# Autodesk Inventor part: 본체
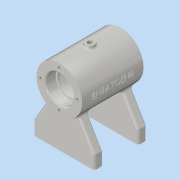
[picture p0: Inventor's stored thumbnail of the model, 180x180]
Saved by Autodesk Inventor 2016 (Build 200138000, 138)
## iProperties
Created: 2018-05
Part Number: 본체
Material: 알루미늄 6061
Document SubType Name: Modeling
Designer: 605-17
Density: 2.7 g/cm^3
Appearance: 알루미늄 - 평지
Mass: 317.791 g
Surface Area: 375.834 cm^2
Volume: 117.701 cm^3
Author: 605-17
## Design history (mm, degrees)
sketch "스케치1"
  geometry: C1 r 26 at (0, 65); 1 further point
  constraints: 1 centre point, 1 vertical alignment
  dimensions: "d0" = 52 diameter of C1; "d1" = 65 distance of point (0, 0) C1.centre
extrude "돌출1" new body sketch "스케치1" stored distance "d2" = 70; taper "d3" = 0 deg
node "작업 평면1"
sketch "스케치3"
  geometry: L1 (-35, 0)-(35, 0); L2 (-35, 0)-(-35, 15); L3 (-35, 15)-(-16.058, 47.808); L4 (-16.058, 47.808)-(16.058, 47.808); L5 (35, 0)-(35, 15); L6 (35, 15)-(16.058, 47.808); 2 further points
  constraints: 12 end point, 2 horizontal, 2 vertical, 1 coincident, 1 midpoint
  dimensions: "d5" = 70 distance of L1.start L1.end; "d6" = 15 distance of L1.start L2.end; "d7" = 30 deg angle of L2 L3; "d8" = 15 distance of L1.end L5.end; "d9" = 30 deg angle of L5 L6; "d10" = 32.11665 distance of L3.end L4.end
extrude "돌출2" join sketch "스케치3" distance "d11" = 10; taper "d12" = 0 deg
sketch "스케치4"
  geometry: L1 (81, 35)-(65, 35); L2 (65, 35)-(65, 23); L3 (65, 23)-(81, 23); L4 (81, 23)-(81, 35); L5 (79, 23)-(65, 23); L6 (65, 23)-(65, 21); L7 (65, 21)-(79, 21); L8 (79, 21)-(79, 23); L9 (86, 21)-(65, 21); L10 (65, 21)-(65, -21); L11 (65, -21)-(86, -21); L12 (86, -21)-(86, 21); L13 (79, -21)-(65, -21); L14 (65, -21)-(65, -23); L15 (65, -23)-(79, -23); L16 (79, -23)-(79, -21); L17 (91, 35)-(39, 35) reference; L18 (81, -23)-(65, -23); L19 (65, -23)-(65, -35); L20 (65, -35)-(81, -35); L21 (81, -35)-(81, -23); 1 further point
  constraints: 40 end point, 10 parallel, 7 collinear, 5 horizontal, 5 perpendicular, 1 midpoint, 1 point on line
  dimensions: "d13" = 12 distance of L1.end L2.end; "d15" = 42 distance of L9.end L10.end; "d16" = 2 distance of L5.end L6.end; "d17" = 2 distance of L13.end L14.end; "d18" = 16 distance of L1.start L1.end; "d19" = 14 distance of L5.start L5.end; "d20" = 21 distance of L9.start L9.end; "d21" = 14 distance of L14.end L15.end; "d22" = 12 distance of L18.end L19.end; "d23" = 16 distance of L19.end L20.end
revolve "회전1" sketch "스케치4" stored, may be unused: angle "d24" = 90 deg
chamfer "모따기1" distance "d25" = 1; stored, may be unused: second distance "d26" = 2, angle "d27" = 45 deg
fillet "모깎기1" dims "d28" = 3
fillet "모깎기2" dims "d29" = 0.3
sketch "스케치5"
  geometry: C1 r 26 at (0, 0) reference; 2 further points
  constraints: 1 vertical alignment
  dimensions: "d30" = 21 distance of C1.centre point (0, 21)
hole "구멍1" sketch "스케치5" at (0, 21) diameter "d31" = 3.242; stored, may be unused: countersink angle "d35" = 90 deg, drill point angle "d37" = 118 deg; dims "d32" = 8, "d33" = 4, "d34" = 2, "d36" = 10
sketch "스케치6"
  geometry: L1 (0, 0)-(70, 0) reference; L2 (0, 0)-(0, 10) reference; 5 further points
  constraints: 1 horizontal, 1 vertical, 3 other
  dimensions: "d41" = 20 horizontal distance of point (35, -20) point (55, 5); "d42" = 25 vertical distance of point (35, -20) point (55, 5); "d45" = 40 distance of point (55, 5) point (15, 5); "d48" = 50 distance of point (55, 5) point (55, -45)
hole "구멍2" sketch "스케치6" at (55, 5), (15, 5), (55, -45), (15, -45) diameter "d51" = 4.134; stored, may be unused: countersink angle "d55" = 90 deg, drill point angle "d57" = 118 deg; dims "d52" = 8, "d53" = 4, "d54" = 2, "d56" = 10
node "작업 평면2"
sketch "스케치7"
  geometry: L1 (0, 0)-(91, 0); L2 (91, -35)-(91, 35) reference; L3 (39, -35)-(91, -35) reference; L4 (65, -35)-(65, 35); L5 (82, 35)-(48, 35) reference; 1 further point
  constraints: 4 end point, 3 midpoint, 1 other
  dimensions: "d59" = 35 distance from line of point (65, 0) L5; "d60" = 26 distance from line of L2 point (65, 0)
feature "엠보싱1" sketch "스케치7" dims "d61" = 0.5, "d62" = 0
node "작업 평면3"
sketch "스케치8"
  geometry: C1 r 5 at (0, 0); 1 further point
  constraints: 1 centre point, 1 coincident
  dimensions: "d64" = 10 diameter of C1
extrude "돌출3" join sketch "스케치8" stored distance "d65" = 5; taper "d66" = 0 deg
sketch "스케치9"
  geometry: C1 r 5 at (0, 0) reference; 1 further point
  constraints: 1 coincident
hole "구멍3" sketch "스케치9" at (0, 0) diameter "d67" = 5.188; stored, may be unused: countersink angle "d71" = 90 deg, drill point angle "d73" = 118 deg; dims "d68" = 12, "d69" = 4, "d70" = 2, "d72" = 16
sketch "스케치10"
  geometry: L1 (48, -35)-(82, -35) reference; L2 (63.379, 35)-(66.621, 35) reference; L3 (65, -33.381)-(65, 33.381); 2 further points
  constraints: 2 end point, 1 horizontal alignment, 1 midpoint, 1 vertical
  dimensions: "d75" = 65 distance from line of point (0, 0) L3; "d76" = 66.7623 distance of L3.start L3.end
node "작업 평면6"
  node "작업 평면5"
sketch "스케치11"
  geometry: L1 (-1.619, 26)-(-1.619, -26) reference; C1 r 6 at (33.381, 0); 2 further points
  constraints: 1 centre point, 1 horizontal alignment, 1 midpoint, 1 vertical alignment
  dimensions: "d80" = 12 diameter of C1
extrude "돌출4" join sketch "스케치11" stored distance "d81" = 5; taper "d82" = 0 deg
sketch "스케치12"
  geometry: C1 r 6 at (0, 0) reference; 2 further points
  constraints: 1 coincident
hole "구멍4" sketch "스케치12" at (0, 0) diameter "d83" = 5.188; stored, may be unused: countersink angle "d87" = 90 deg, drill point angle "d89" = 118 deg; dims "d84" = 13, "d85" = 4, "d86" = 2, "d88" = 17
fillet "모깎기3" dims "d90" = 2
fillet "모깎기4" dims "d91" = 3
fillet "모깎기5" dims "d92" = 3
node "솔리드1"
mirror "대칭1"
pattern_circular "원형 패턴1" dims angle "d39" = 360 deg
mirror "대칭2"
node "작업 평면4"
other parameters: "d58" = 63, "d63" = 94, "d77" = 65, "d78" = -20 deg, "d79" = -29
